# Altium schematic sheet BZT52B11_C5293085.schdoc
size 127 x 101 mm
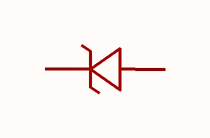
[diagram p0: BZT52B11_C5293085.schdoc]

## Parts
D?  bzt52b11_c5293085  [SOD-123_L2.7-W1.6-LS3.7-RD]  (value not drawn)

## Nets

Not connected (* = marked no-connect by the designer): D? 1(C) 2(A)

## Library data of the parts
D? = bzt52b11_c5293085: 二极管配置:1个独立式;稳压值(标称值):11V;稳压值(范围值):10.28V~11.22V;耗散功率(Pd):500mW;; Manufacturer: CJ(江苏长电/长晶); AddInBom: yes; ModelId: ad7e39f9e5534b3c96ffdc5532ebb493; ModelName: SOD-123_L2.7-W1.6-H1.4-LS3.7; ModelTransform: 146.026,62.992,0,180,0,0,0.0005,0,0; Diode Configuration: 1个独立式; Zener Voltage(Nom): 11V; Reverse Leakage Current (Ir): 100nA; Pd - Power Dissipation: 500mW; Impedance(Zzt): 20Ω; Impedance(Zzk): 150Ω; Operating Junction Temperature Range: -55℃~+150℃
